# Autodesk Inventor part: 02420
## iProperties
Author: Administrator
Shininess: 64.0
Angle Display Precision: 2
Document Length Units: 11272
Document Angle Units: 11286
Document Time Units: 11279
Document Mass Units: 11290
Document Length Units Precision: 3
Document Angle Units Precision: 2
Compacted: True
PropertySet Name: _Private Model Information
Created: 2002-04
Part Number: 02420
Material: Stainless Steel, 440C
Document SubType Name: Modeling
Designer: Administrator
Control State: 0
Master: False
Checked Out: False
PropertySet Name: Design Tracking Control
Density: 0.0
Volumn: 0.0
Area: 0.0
PropertySet Name: Model Information
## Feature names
1. Revolution1
